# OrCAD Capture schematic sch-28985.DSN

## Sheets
1 1. Title Page: title: BRKTSTBC-P3115; rev: A; company: Freescale Semiconductor; note: SCH-28985 PDF: SPF-28985; note: 6501 William Cannon Drive West; note: Austin, TX 78735-8598
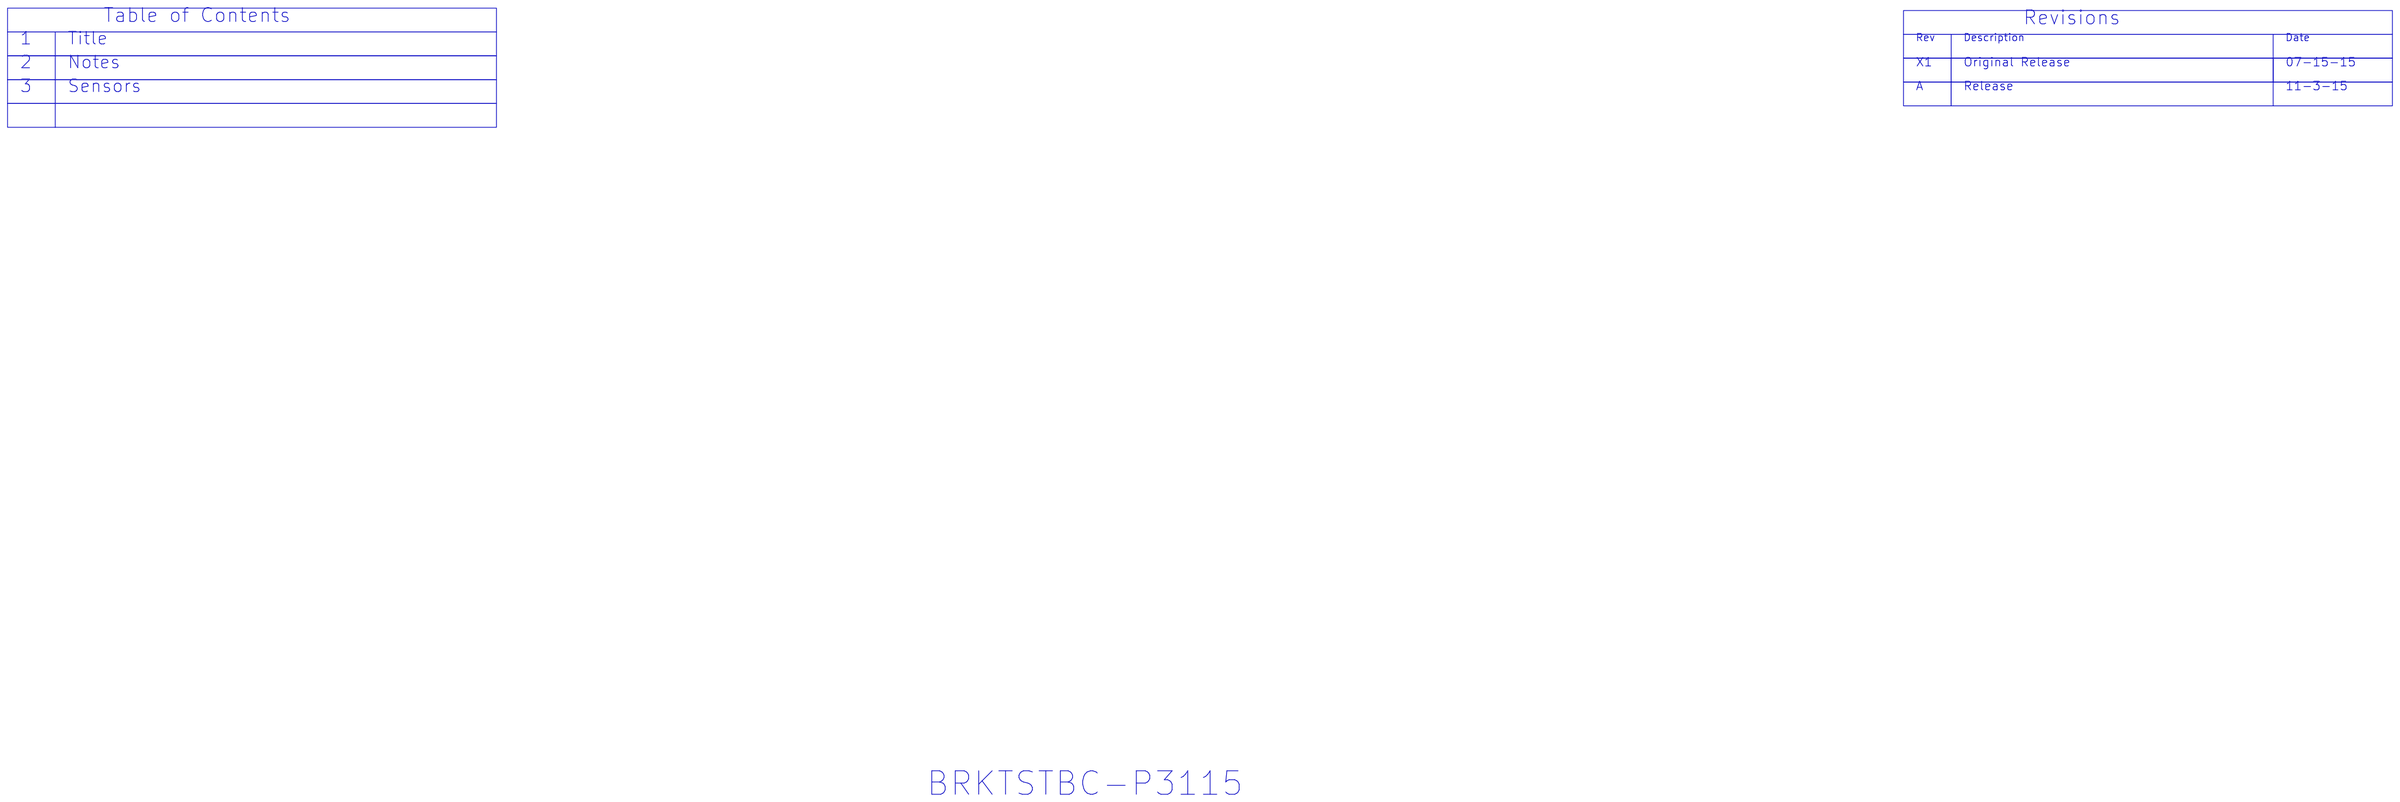
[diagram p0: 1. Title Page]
2 2. Notes
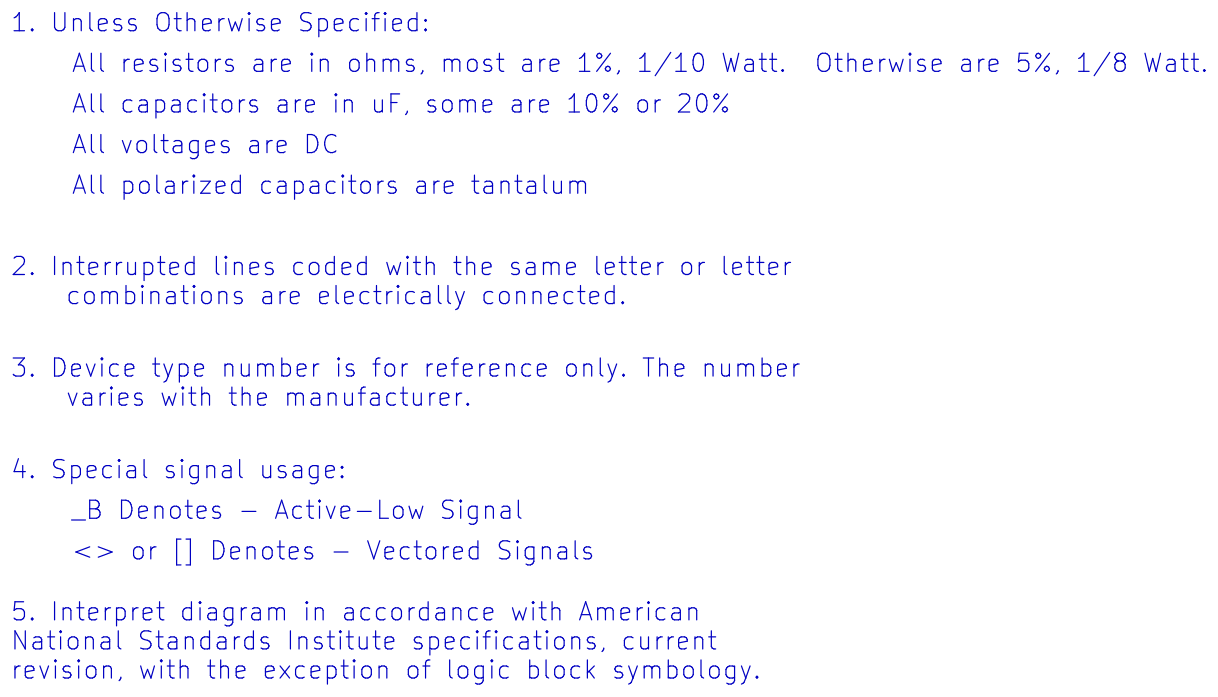
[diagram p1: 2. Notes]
3 3. Sensors: size C
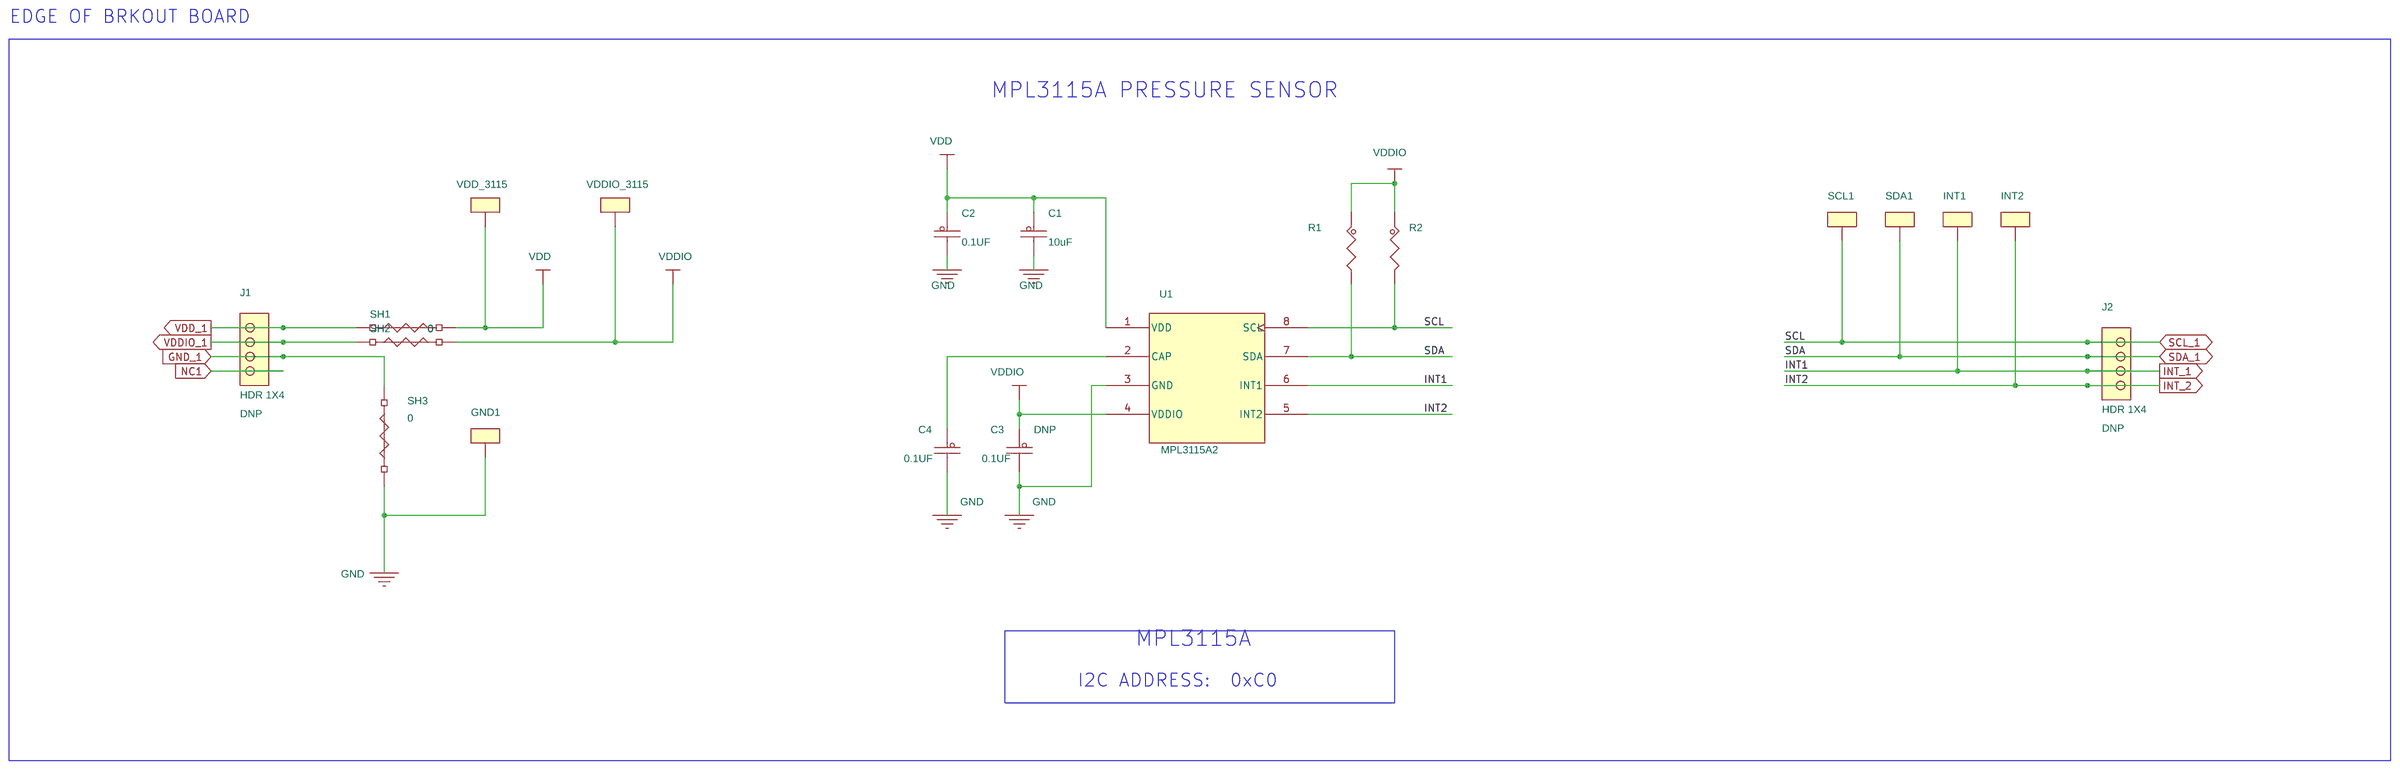
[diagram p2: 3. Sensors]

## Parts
C1  10uF  [CC0402_25]
C2  0.1UF  [CC0402_25]
C3  0.1UF  [CC0402_25]
C4  0.1UF  [CC0402_25]
GND1  0805  [testpoint_122x049mil]
INT1  0805  [testpoint_122x049mil]
INT2  0805  [testpoint_122x049mil]
J1  HDR 1X4  [HDR104]
J2  HDR 1X4  [HDR104]
R1  4.7K  [RC0603]
R2  4.7K  [RC0603]
SCL1  0805  [testpoint_122x049mil]
SDA1  0805  [testpoint_122x049mil]
SH1  0  [SH0201]
SH2  0  [SH0201]
SH3  0  [SH0201]
U1  MPL3115A2  [LGA8_1P25_3X5_0P5]
VDD_3115  0805  [testpoint_122x049mil]
VDDIO_3115  0805  [testpoint_122x049mil]

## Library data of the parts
C1 = CAP_NP: CAP CER 10uF 10V 20% X5R 0402; AGILE_PN: 150-79255; CAD_APPROVED: Yes; FPLIST: CC0402_25,CC0402_HD,0402_CC; HEIGHT: 0.7MM; MFG_NAME01: SAMSUNG; MFG_PN01: CL05A106MP5NUNC; ROHS: Yes; Tolerance: 20%; VOLTAGE: 10V
C2 C4 = CAP_NP: CAP CER 0.1UF 10V 10% X5R 0402; AGILE_PN: 150-75634; CAD_APPROVED: Yes; FPLIST: CC0402_25,CC0402_HD,0402_CC; HEIGHT: 0.64MM; MFG_NAME01: KEMET; MFG_PN01: C0402C104K8PAC; ROHS: Yes; Tolerance: 10%; VOLTAGE: 10V
C3 = CAP_NP: CAP CER 0.1UF 10V 10% X5R 0402; AGILE_PN: 150-75634; ASSY_OPT: DNP; CAD_APPROVED: Yes; FPLIST: CC0402_25,CC0402_HD,0402_CC; HEIGHT: 0.64MM; MFG_NAME01: KEMET; MFG_PN01: C0402C104K8PAC; ROHS: Yes; Tolerance: 10%; VOLTAGE: 10V
GND1 INT1 INT2 SCL1 SDA1 VDD_3115 VDDIO_3115 = TEST_POINT: TEST POINT PAD 3.1MMX1.25MM SMT AEC-Q200 0805; AGILE_PN: 211-79608; CAD_APPROVED: Yes; HEIGHT: 1.45MM; MFG_NAME01: KOA Speer; MFG_PN01: RCTCTE; ROHS: Yes
J1 J2 = CONN_HDR_4X1: HDR 1X4 TH 100MIL SP 374H AU 164L; AGILE_PN: 210-80024; ASSY_OPT: DNP; CAD_APPROVED: Yes; HEIGHT: 9.5MM; MFG_NAME01: SAMTEC; MFG_PN01: HMTSW-104-08-G-S-266; ROHS: Yes
R1 R2 = RES: RES MF 4.7K 1/10W 5% 0603; AGILE_PN: 470-75414; CAD_APPROVED: Yes; FPLIST: RC0603_OV,RC0603,0603_CC; HEIGHT: 0.55 MM; MFG_NAME01: VISHAY INTERTECHNOLOGY; MFG_PN01: CRCW06034K70JNEA; ROHS: Yes; Tolerance: 5%
SH1-SH3 = RES_SHORT-2: ZERO OHM CUT TRACE 0201 PADS; NO PART TO ORDER; AGILE_PN: 470-76473; CAD_APPROVED: Yes; FPLIST: SH0201,SH0201_CC; HEIGHT: 0.1 MM; MFG_NAME01: LAYOUT ELEMENT ONLY; MFG_PN01: LAYOUT ELEMENT ONLY; ROHS: Yes
U1 = PPL3115A2_LGA_8P: IC ALTIMETER I2C 50-115KPA 1.96-3.6V LGA8; AGILE_PN: 315-79136; CAD_APPROVED: Yes; HEIGHT: 1.2MM; MFG_NAME01: FREESCALE SEMICONDUCTOR; ROHS: Yes

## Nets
GND: C1.2 C2.2 C3.2 C4.2 GND1.1 SH3.1 U1.3(GND)
GND_1: J1.3 SH3.2
VDD: C1.1 C2.1 SH1.2 U1.1(VDD) VDD_3115.1
VDD_1: J1.1 SH1.1
VDDIO: C3.1 R1.1 R2.1 SH2.2 U1.4(VDDIO) VDDIO_3115.1
VDDIO_1: J1.2 SH2.1
INT_1: INT1.1 J2.3 U1.6(INT1)
INT_2: INT2.1 J2.4 U1.5(INT2)
NC1: J1.4
SCL_1: J2.1 R2.2 SCL1.1 U1.8(SCL)
SDA_1: J2.2 R1.2 SDA1.1 U1.7(SDA)
N16859277: C4.1 U1.2(CAP)

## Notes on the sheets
sheet 1
- Table of Contents
- Revisions
- 1
- Title
- Rev
- Description
- Date
- 2
- Notes
- X1
- Original Release
- 07-15-15
- 3
- Sensors
- A
- Release
- 11-3-15
- BRKTSTBC-P3115
sheet 2
- 1. Unless Otherwise Specified:
- All resistors are in ohms, most are 1%, 1/10 Watt.  Otherwise are 5%, 1/8 Watt.
- All capacitors are in uF, some are 10% or 20%
- All voltages are DC
- All polarized capacitors are tantalum
- 2. Interrupted lines coded with the same letter or letter
      combinations are electrically connected.
- 3. Device type number is for reference only. The number
      varies with the manufacturer.
- 4. Special signal usage:
- _B Denotes - Active-Low Signal
- <> or [] Denotes - Vectored Signals
- 5. Interpret diagram in accordance with American
  National Standards Institute specifications, current
  revision, with the exception of logic block symbology.
sheet 3
- EDGE OF BRKOUT BOARD
- MPL3115A PRESSURE SENSOR
- MPL3115A
- I2C ADDRESS:  0xC0
